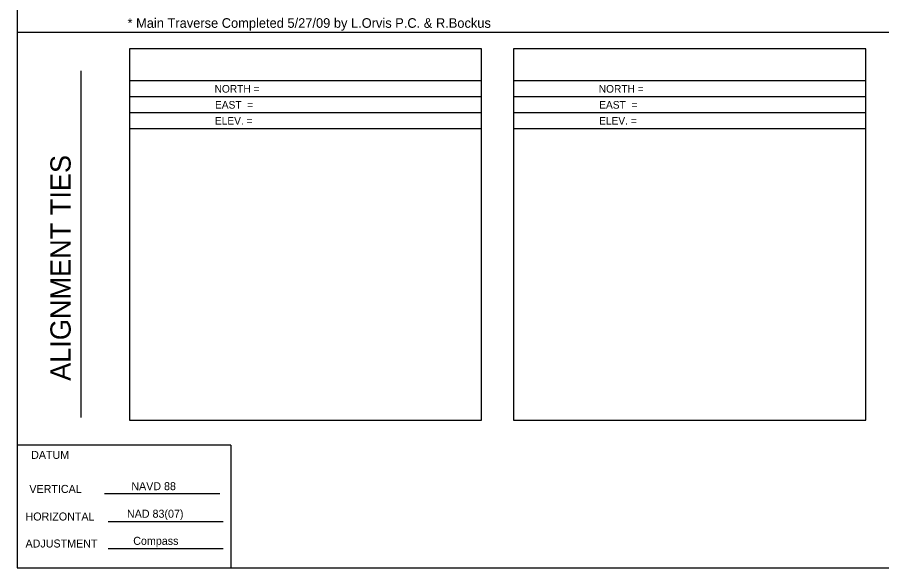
# Model space of a CAD drawing. Extents: x 1454512 to 1455152, y 715836 to 716256.
# Drawn here: x 1454512.2 to 1454782.2, y 715835.5 to 716007.5 of the extents above; entities that cross this region are included whole.
import ezdxf

# ---------------------------------------------------------------- set-up
doc = ezdxf.new("R2010")
doc.units = 0
for name, color, linetype in [('Default', 7, 'Continuous'), ('NBL1', 7, 'Continuous'), ('NBL2', 7, 'Continuous')]:
    doc.layers.add(name, color=color, linetype=linetype)

msp = doc.modelspace()

# ---------------------------------------------------------------- linework, layer by layer
at = {"layer": 'NBL1'}
msp.add_lwpolyline([(1454512.16, 715835.51), (1455152.16, 715835.51), (1455152.16, 716255.51), (1454512.16, 716255.51)], close=True, dxfattribs=at)
at = {"layer": 'NBL2'}
for p, q in [((1454512.16, 716002.85), (1455152.16, 716002.85)), ((1454532.16, 715882.51), (1454532.16, 715990.85)), ((1454657.16, 715987.68), (1454547.16, 715987.68)), ((1454777.16, 715987.68), (1454667.16, 715987.68)), ((1454657.16, 715982.68), (1454547.16, 715982.68)), ((1454777.16, 715982.68), (1454667.16, 715982.68)), ((1454657.16, 715977.68), (1454547.16, 715977.68)), ((1454777.16, 715977.68), (1454667.16, 715977.68)), ((1454657.16, 715972.68), (1454547.16, 715972.68)), ((1454777.16, 715972.68), (1454667.16, 715972.68)), ((1454578.83, 715873.77), (1454512.16, 715873.77)), ((1454578.83, 715873.77), (1454578.83, 715835.51)), ((1454578.83, 715873.77), (1454578.83, 715835.51)), ((1454539.4, 715858.74), (1454575.4, 715858.71)), ((1454540.51, 715849.97), (1454576.51, 715849.97)), ((1454540.51, 715841.53), (1454576.51, 715841.5))]:
    msp.add_line(p, q, dxfattribs=at)
for points in [[(1454547.16, 715881.68), (1454657.16, 715881.68), (1454657.16, 715997.68), (1454547.16, 715997.68)], [(1454667.16, 715881.68), (1454777.16, 715881.68), (1454777.16, 715997.68), (1454667.16, 715997.68)]]:
    msp.add_lwpolyline(points, close=True, dxfattribs=at)

# ---------------------------------------------------------------- texts
at = {"layer": 'Default'}
msp.add_text('* Main Traverse Completed 5/27/09 by L.Orvis P.C. & R.Bockus', height=3, dxfattribs=at).set_placement((1454546.6, 716004.25))
at = {"layer": 'NBL2'}
for s, height, p in [('NORTH =             ', 2.375, (1454573.78, 715983.99)), ('NORTH =             ', 2.375, (1454693.78, 715983.99)), ('EAST  =             ', 2.375, (1454573.92, 715978.99)), ('EAST  =             ', 2.375, (1454693.92, 715978.99)), ('ELEV. =             ', 2.375, (1454573.89, 715973.99)), ('ELEV. =             ', 2.375, (1454693.89, 715973.99)), ('DATUM', 2.5, (1454516.48, 715869.53)), ('  NAVD 88 ', 2.5, (1454545.92, 715859.75)), ('HORIZONTAL', 2.5, (1454514.73, 715850.27)), ('NAD 83(07) ', 2.5, (1454546.42, 715851.14)), ('  Compass ', 2.5, (1454546.52, 715842.66)), ('ADJUSTMENT', 2.5, (1454514.73, 715841.83))]:
    msp.add_text(s, height=height, dxfattribs=at).set_placement(p)
for s, height, rotation, p in [('ALIGNMENT TIES', 6.3332, 90, (1454528.83, 715893.92)), ('VERTICAL', 2.5, 0.1439, (1454515.94, 715858.86))]:
    msp.add_text(s, height=height, rotation=rotation, dxfattribs=at).set_placement(p)

doc.saveas('drawing.dxf')
